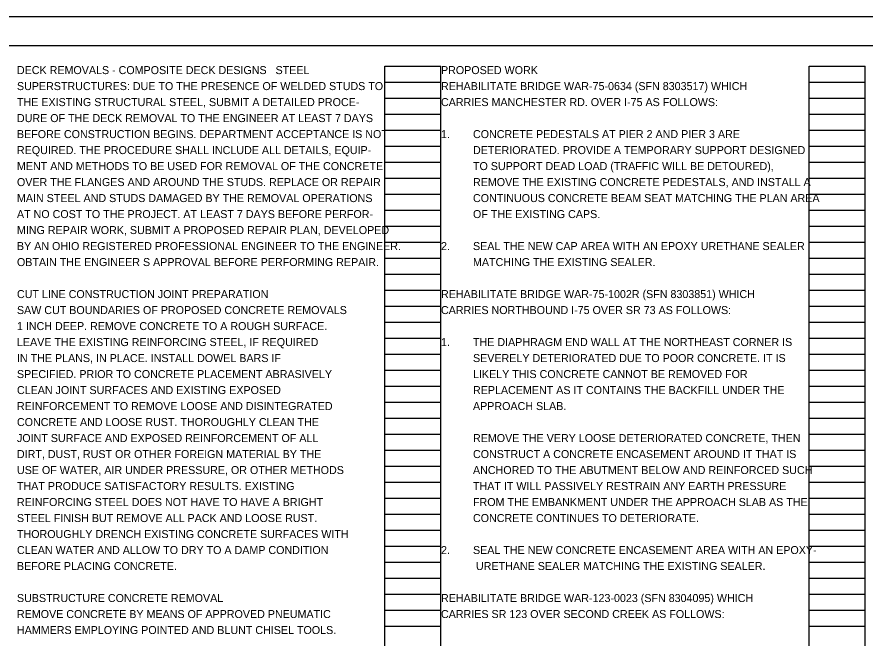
# Model space of a CAD drawing. Extents: x -11.4 to 50.8, y -16 to 31.7.
# Drawn here: x 9.82 to 24.66, y 11.13 to 22 of the extents above; entities that cross this region are included whole.
import ezdxf

# ---------------------------------------------------------------- set-up
doc = ezdxf.new("R2010")
doc.units = 0
for name, color, linetype in [('SC_Scratch1', 7, 'Continuous'), ('SH_Border', 7, 'Continuous'), ('SH_Cut_Line', 7, 'Continuous'), ('SH_Text', 7, 'Continuous')]:
    doc.layers.add(name, color=color, linetype=linetype)

msp = doc.modelspace()

# ---------------------------------------------------------------- linework, layer by layer
at = {"layer": 'SC_Scratch1'}
for p, q in [((16.26, 0.98), (16.26, 21.14)), ((16.26, 21.14), (17.24, 21.14)), ((17.24, 0.98), (17.24, 21.14)), ((23.68, 0.98), (23.68, 21.14)), ((23.68, 21.14), (24.66, 21.14)), ((24.66, 0.98), (24.66, 21.14)), ((16.26, 20.86), (17.24, 20.86)), ((23.68, 20.86), (24.66, 20.86)), ((16.26, 20.58), (17.24, 20.58)), ((23.68, 20.58), (24.66, 20.58)), ((16.26, 20.3), (17.24, 20.3)), ((23.68, 20.3), (24.66, 20.3)), ((16.26, 20.02), (17.24, 20.02)), ((23.68, 20.02), (24.66, 20.02)), ((16.26, 19.74), (17.24, 19.74)), ((23.68, 19.74), (24.66, 19.74)), ((16.26, 19.46), (17.24, 19.46)), ((23.68, 19.46), (24.66, 19.46)), ((16.26, 19.18), (17.24, 19.18)), ((23.68, 19.18), (24.66, 19.18)), ((16.26, 18.9), (17.24, 18.9)), ((23.68, 18.9), (24.66, 18.9)), ((16.26, 18.62), (17.24, 18.62)), ((23.68, 18.62), (24.66, 18.62)), ((16.26, 18.34), (17.24, 18.34)), ((23.68, 18.34), (24.66, 18.34)), ((16.26, 18.06), (17.24, 18.06)), ((23.68, 18.06), (24.66, 18.06)), ((16.26, 17.78), (17.24, 17.78)), ((23.68, 17.78), (24.66, 17.78)), ((16.26, 17.5), (17.24, 17.5)), ((23.68, 17.5), (24.66, 17.5)), ((16.26, 17.22), (17.24, 17.22)), ((23.68, 17.22), (24.66, 17.22)), ((16.26, 16.94), (17.24, 16.94)), ((23.68, 16.94), (24.66, 16.94)), ((16.26, 16.66), (17.24, 16.66)), ((23.68, 16.66), (24.66, 16.66)), ((16.26, 16.38), (17.24, 16.38)), ((23.68, 16.38), (24.66, 16.38)), ((16.26, 16.1), (17.24, 16.1)), ((23.68, 16.1), (24.66, 16.1)), ((16.26, 15.82), (17.24, 15.82)), ((23.68, 15.82), (24.66, 15.82)), ((16.26, 15.54), (17.24, 15.54)), ((23.68, 15.54), (24.66, 15.54)), ((16.26, 15.26), (17.24, 15.26)), ((23.68, 15.26), (24.66, 15.26)), ((16.26, 14.98), (17.24, 14.98)), ((23.68, 14.98), (24.66, 14.98)), ((16.26, 14.7), (17.24, 14.7)), ((23.68, 14.7), (24.66, 14.7)), ((16.26, 14.42), (17.24, 14.42)), ((23.68, 14.42), (24.66, 14.42)), ((16.26, 14.14), (17.24, 14.14)), ((23.68, 14.14), (24.66, 14.14)), ((16.26, 13.86), (17.24, 13.86)), ((23.68, 13.86), (24.66, 13.86)), ((16.26, 13.58), (17.24, 13.58)), ((23.68, 13.58), (24.66, 13.58)), ((16.26, 13.3), (17.24, 13.3)), ((23.68, 13.3), (24.66, 13.3)), ((16.26, 13.02), (17.24, 13.02)), ((23.68, 13.02), (24.66, 13.02)), ((16.26, 12.74), (17.24, 12.74)), ((23.68, 12.74), (24.66, 12.74)), ((16.26, 12.46), (17.24, 12.46)), ((23.68, 12.46), (24.66, 12.46)), ((16.26, 12.18), (17.24, 12.18)), ((23.68, 12.18), (24.66, 12.18)), ((16.26, 11.9), (17.24, 11.9)), ((23.68, 11.9), (24.66, 11.9)), ((16.26, 11.62), (17.24, 11.62)), ((23.68, 11.62), (24.66, 11.62)), ((16.26, 11.34), (17.24, 11.34)), ((23.68, 11.34), (24.66, 11.34))]:
    msp.add_line(p, q, dxfattribs=at)
at = {"layer": 'SH_Border'}
msp.add_lwpolyline([(1.5, 21.5), (33.5, 21.5), (33.5, 0.5), (1.5, 0.5)], close=True, dxfattribs=at)
at = {"layer": 'SH_Cut_Line'}
msp.add_lwpolyline([(0, 0), (34, 0), (34, 22), (0, 22)], close=True, dxfattribs=at)

# ---------------------------------------------------------------- texts
at = {"layer": 'SH_Text'}
for s, p in [('DECK REMOVALS - COMPOSITE DECK DESIGNS   STEEL', (9.82, 21)), ('PROPOSED WORK', (17.24, 21)), ('SUPERSTRUCTURES: DUE TO THE PRESENCE OF WELDED STUDS TO', (9.82, 20.72)), ('REHABILITATE BRIDGE WAR-75-0634 (SFN 8303517) WHICH ', (17.24, 20.72)), ('THE EXISTING STRUCTURAL STEEL, SUBMIT A DETAILED PROCE-', (9.82, 20.44)), ('CARRIES MANCHESTER RD. OVER I-75 AS FOLLOWS: ', (17.24, 20.44)), ('DURE OF THE DECK REMOVAL TO THE ENGINEER AT LEAST 7 DAYS', (9.82, 20.16)), ('BEFORE CONSTRUCTION BEGINS. DEPARTMENT ACCEPTANCE IS NOT', (9.82, 19.88)), ('1.', (17.24, 19.88)), ('CONCRETE PEDESTALS AT PIER 2 AND PIER 3 ARE', (17.8, 19.88)), ('REQUIRED. THE PROCEDURE SHALL INCLUDE ALL DETAILS, EQUIP-', (9.82, 19.6)), ('DETERIORATED. PROVIDE A TEMPORARY SUPPORT DESIGNED', (17.8, 19.6)), ('MENT AND METHODS TO BE USED FOR REMOVAL OF THE CONCRETE', (9.82, 19.32)), ('TO SUPPORT DEAD LOAD (TRAFFIC WILL BE DETOURED),', (17.8, 19.32)), ('OVER THE FLANGES AND AROUND THE STUDS. REPLACE OR REPAIR', (9.82, 19.04)), ('REMOVE THE EXISTING CONCRETE PEDESTALS, AND INSTALL A', (17.8, 19.04)), ('MAIN STEEL AND STUDS DAMAGED BY THE REMOVAL OPERATIONS', (9.82, 18.76)), ('CONTINUOUS CONCRETE BEAM SEAT MATCHING THE PLAN AREA', (17.8, 18.76)), ('AT NO COST TO THE PROJECT. AT LEAST 7 DAYS BEFORE PERFOR-', (9.82, 18.48)), ('OF THE EXISTING CAPS.', (17.8, 18.48)), ('MING REPAIR WORK, SUBMIT A PROPOSED REPAIR PLAN, DEVELOPED', (9.82, 18.2)), ('BY AN OHIO REGISTERED PROFESSIONAL ENGINEER TO THE ENGINEER.', (9.82, 17.92)), ('2.', (17.24, 17.92)), ('SEAL THE NEW CAP AREA WITH AN EPOXY URETHANE SEALER', (17.8, 17.92)), ('OBTAIN THE ENGINEER S APPROVAL BEFORE PERFORMING REPAIR.', (9.82, 17.64)), ('MATCHING THE EXISTING SEALER.', (17.8, 17.64)), ('CUT LINE CONSTRUCTION JOINT PREPARATION', (9.82, 17.08)), ('REHABILITATE BRIDGE WAR-75-1002R (SFN 8303851) WHICH ', (17.24, 17.08)), ('SAW CUT BOUNDARIES OF PROPOSED CONCRETE REMOVALS', (9.82, 16.8)), ('CARRIES NORTHBOUND I-75 OVER SR 73 AS FOLLOWS: ', (17.24, 16.8)), ('1 INCH DEEP. REMOVE CONCRETE TO A ROUGH SURFACE.', (9.82, 16.52)), ('LEAVE THE EXISTING REINFORCING STEEL, IF REQUIRED', (9.82, 16.24)), ('1.', (17.24, 16.24)), ('THE DIAPHRAGM END WALL AT THE NORTHEAST CORNER IS', (17.8, 16.24)), ('IN THE PLANS, IN PLACE. INSTALL DOWEL BARS IF', (9.82, 15.96)), ('SEVERELY DETERIORATED DUE TO POOR CONCRETE. IT IS', (17.8, 15.96)), ('SPECIFIED. PRIOR TO CONCRETE PLACEMENT ABRASIVELY', (9.82, 15.68)), ('LIKELY THIS CONCRETE CANNOT BE REMOVED FOR', (17.8, 15.68)), ('CLEAN JOINT SURFACES AND EXISTING EXPOSED', (9.82, 15.4)), ('REPLACEMENT AS IT CONTAINS THE BACKFILL UNDER THE', (17.8, 15.4)), ('REINFORCEMENT TO REMOVE LOOSE AND DISINTEGRATED', (9.82, 15.12)), ('APPROACH SLAB. ', (17.8, 15.12)), ('CONCRETE AND LOOSE RUST. THOROUGHLY CLEAN THE', (9.82, 14.84)), ('JOINT SURFACE AND EXPOSED REINFORCEMENT OF ALL', (9.82, 14.56)), ('REMOVE THE VERY LOOSE DETERIORATED CONCRETE, THEN', (17.8, 14.56)), ('DIRT, DUST, RUST OR OTHER FOREIGN MATERIAL BY THE', (9.82, 14.28)), ('CONSTRUCT A CONCRETE ENCASEMENT AROUND IT THAT IS', (17.8, 14.28)), ('USE OF WATER, AIR UNDER PRESSURE, OR OTHER METHODS', (9.82, 14)), ('ANCHORED TO THE ABUTMENT BELOW AND REINFORCED SUCH', (17.8, 14)), ('THAT PRODUCE SATISFACTORY RESULTS. EXISTING', (9.82, 13.72)), ('THAT IT WILL PASSIVELY RESTRAIN ANY EARTH PRESSURE', (17.8, 13.72)), ('REINFORCING STEEL DOES NOT HAVE TO HAVE A BRIGHT', (9.82, 13.44)), ('FROM THE EMBANKMENT UNDER THE APPROACH SLAB AS THE', (17.8, 13.44)), ('STEEL FINISH BUT REMOVE ALL PACK AND LOOSE RUST.', (9.82, 13.16)), ('CONCRETE CONTINUES TO DETERIORATE.', (17.8, 13.16)), ('THOROUGHLY DRENCH EXISTING CONCRETE SURFACES WITH', (9.82, 12.88)), ('CLEAN WATER AND ALLOW TO DRY TO A DAMP CONDITION', (9.82, 12.6)), ('2.', (17.24, 12.6)), ('SEAL THE NEW CONCRETE ENCASEMENT AREA WITH AN EPOXY-', (17.8, 12.6)), ('BEFORE PLACING CONCRETE.', (9.82, 12.32)), (' URETHANE SEALER MATCHING THE EXISTING SEALER.', (17.8, 12.32)), ('SUBSTRUCTURE CONCRETE REMOVAL', (9.82, 11.76)), ('REHABILITATE BRIDGE WAR-123-0023 (SFN 8304095) WHICH ', (17.24, 11.76)), ('REMOVE CONCRETE BY MEANS OF APPROVED PNEUMATIC', (9.82, 11.48)), ('CARRIES SR 123 OVER SECOND CREEK AS FOLLOWS:', (17.24, 11.48)), ('HAMMERS EMPLOYING POINTED AND BLUNT CHISEL TOOLS.', (9.82, 11.2))]:
    msp.add_text(s, height=0.14, dxfattribs=at).set_placement(p)

doc.saveas('drawing.dxf')
